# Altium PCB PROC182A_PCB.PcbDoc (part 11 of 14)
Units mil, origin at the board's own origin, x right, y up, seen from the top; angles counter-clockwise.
Board outline 3168.31 x 3700.79 mil, 8 copper layers (Top Layer, L2_GND1, L3_SIG1, L4_PWR1, L5_PWR2, L6_SIG2, L7_GND2, Bottom Layer), stack 58.1 mil thick; 580 components, 391 nets, 8314 pads, 4370 vias.
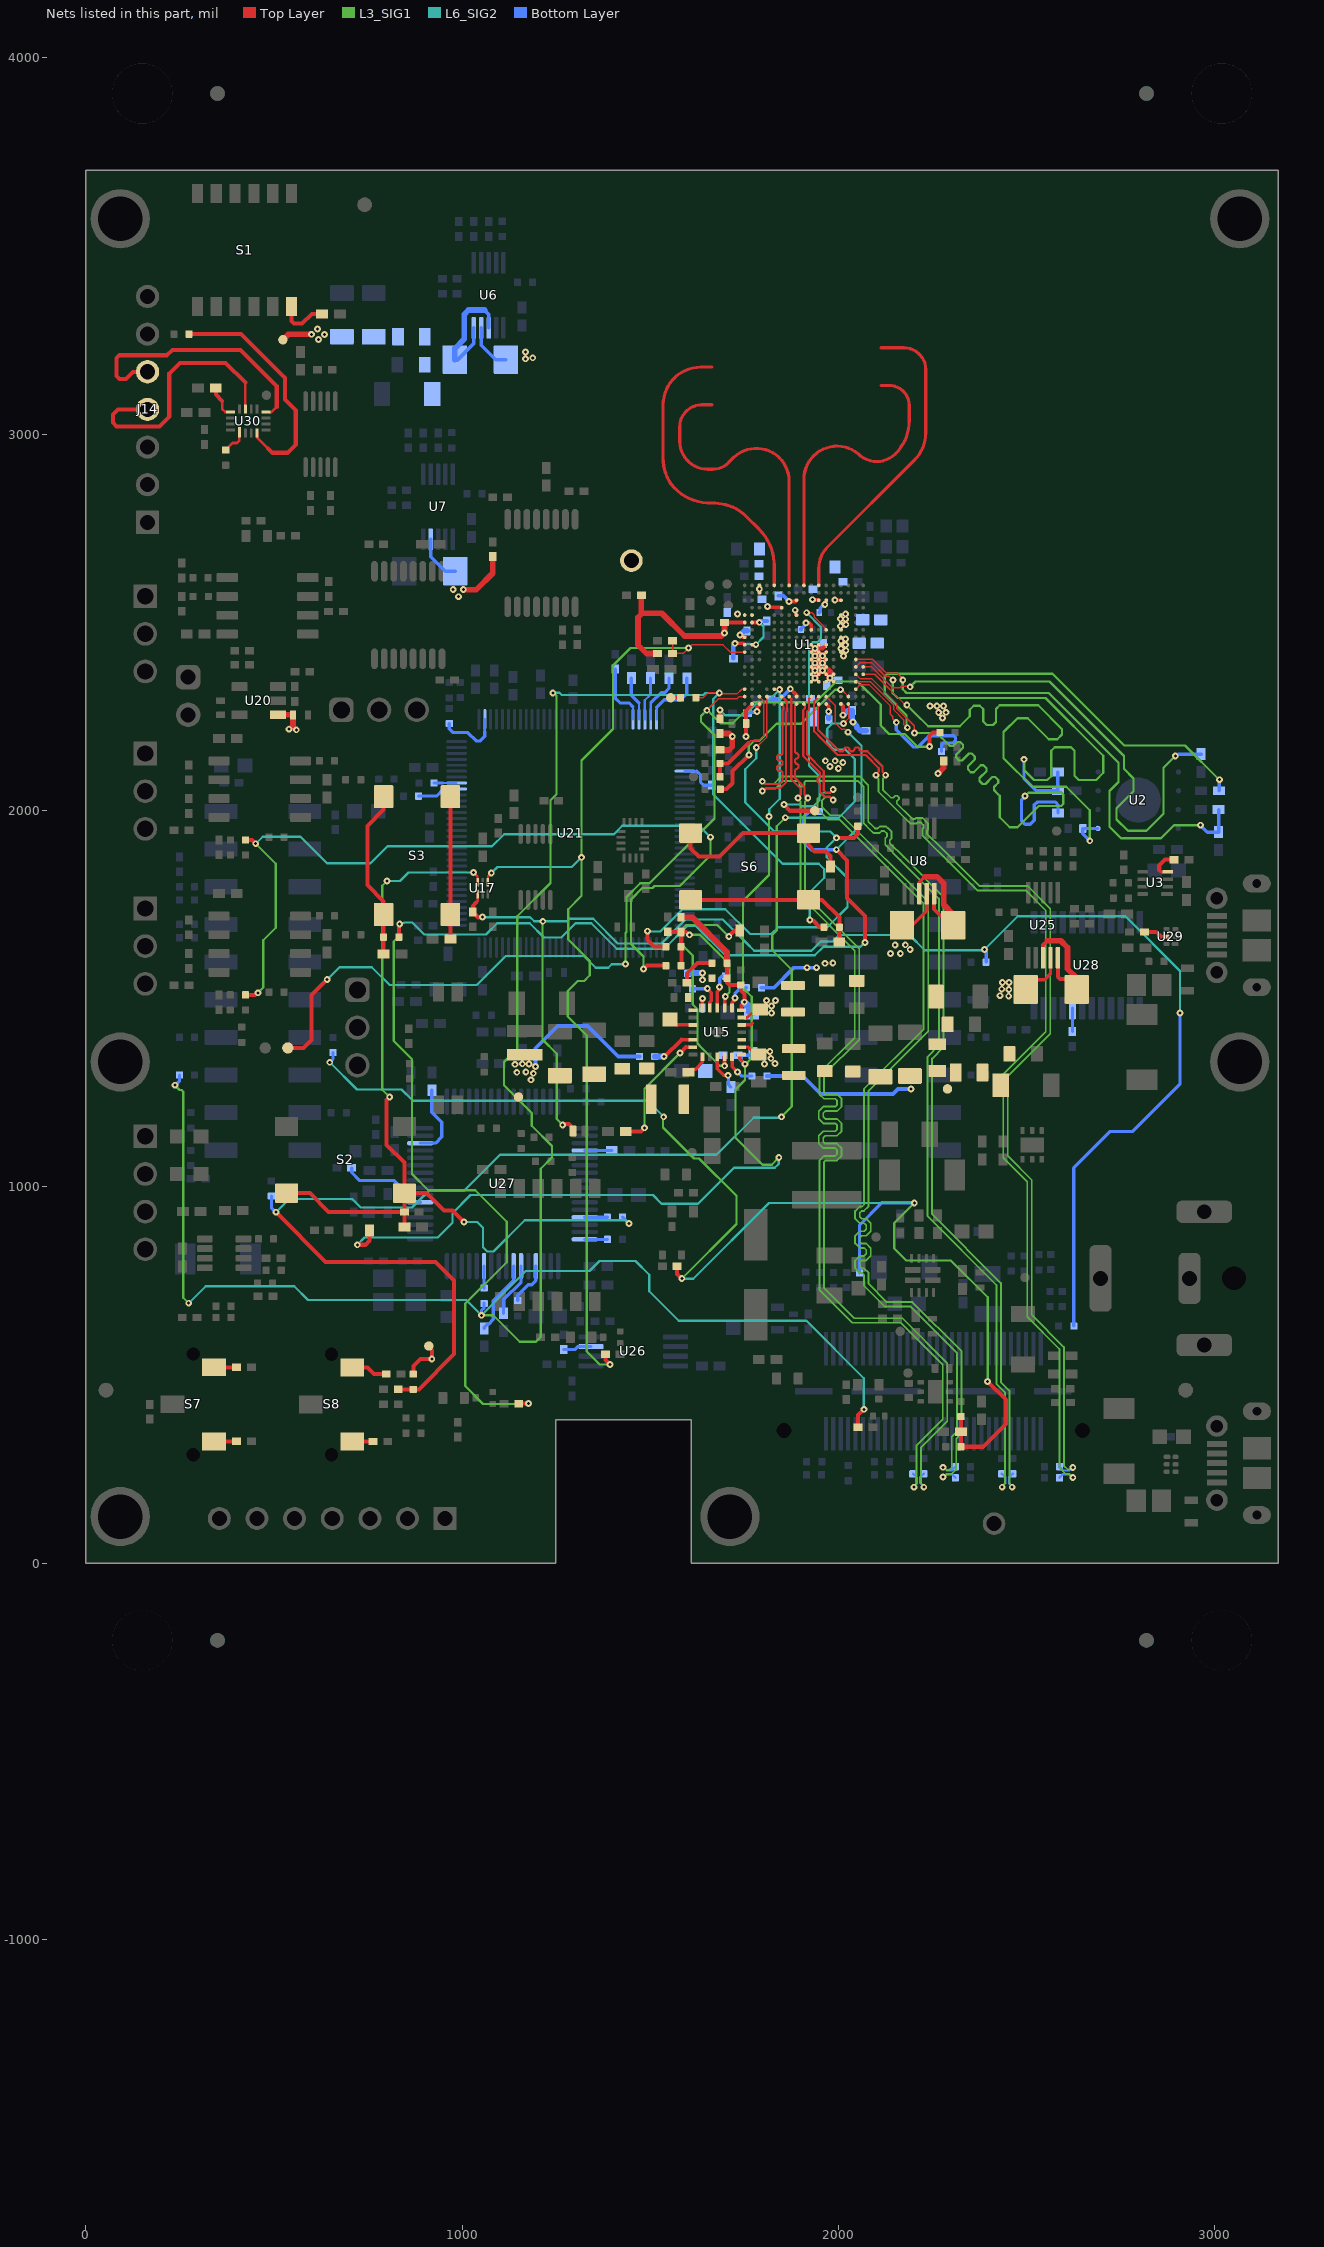
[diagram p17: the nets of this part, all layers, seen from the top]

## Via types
v1: diameter 13.77, hole 7, Top Layer to L2_GND1, tented both sides, 3444 vias
v2: diameter 18, hole 8, Top Layer to Bottom Layer, tented both sides, 911 vias
v3: diameter 13.77, hole 7, Top Layer to L2_GND1, tented top, 9 vias
v4: diameter 19.68, hole 7.87, Top Layer to Bottom Layer, 4 vias
v5: diameter 19.68, hole 7.87, Top Layer to Bottom Layer, tented both sides, 2 vias

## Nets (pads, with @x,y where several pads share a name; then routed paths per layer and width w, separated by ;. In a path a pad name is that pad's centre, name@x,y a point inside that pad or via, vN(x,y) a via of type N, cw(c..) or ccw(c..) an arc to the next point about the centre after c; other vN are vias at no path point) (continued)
NetR185_2: R185.2 U26.3 | length 75.6
  Bottom Layer w8.7: R185.2@1270.18,567.94 1298.89,567.94 1306.87,575.92 U26.3@1342.51,575.92
NetR188_2: R188.2 U21.34 | length 171.5
  Bottom Layer w7: 1060.16,2210.26 1060.11,2210.31 1060.11,2242.42 U21.34@1060.16,2242.47
  Bottom Layer w8.7: R188.2@966.13,2231.17 966.13,2217.65 976.5,2207.27 1015.09,2207.27 1037.42,2184.95 1047.94,2184.95 1060.16,2197.17 1060.16,2210.26
NetR190_2: R190.2 U21.25 | length 60
  Bottom Layer w6: 949.41,2073.18 U21.25@985.36,2073.18
  Bottom Layer w8.7: R190.2@925.36,2073.18 949.41,2073.18
NetR191_1: R191.1 U21.63 | length 168.5
  Bottom Layer w6: U21.63@1516.86,2242.47 1516.86,2274.16
  Bottom Layer w8.7: 1516.86,2274.16 1536.79,2294.09 1581.41,2294.09 1596.96,2309.64 R191.1@1596.96,2351.67
NetR194_1: R194.1 U21.62 | length 135.1
  Bottom Layer w6: U21.62@1501.11,2242.47 1501.11,2281.03 1501.11,2285.87 1502.71,2287.47
  Bottom Layer w8.7: 1502.71,2287.47 1528.71,2313.47 1538.72,2313.47 1549.54,2324.29 R194.1@1549.54,2351.67
NetR195_1: R195.1 U21.61 | length 115.7
  Bottom Layer w6: U21.61@1485.36,2242.47 1485.36,2293.14 1500.19,2307.97 1500.19,2309.96
  Bottom Layer w8.7: 1500.19,2309.96 R195.1@1500.19,2352.01
NetR196_1: R196.1 U21.60 | length 117.8
  Bottom Layer w6: U21.60@1469.61,2242.47 1469.61,2286.77
  Bottom Layer w8.7: R196.1@1449.62,2352.01 1449.62,2306.76 1469.61,2286.77
NetR204_1: R204.1 S7.3 | length 60
  Top Layer w10.8: S7.3@340.69,520.9 R204.1@400.69,520.9
NetR205_2: R205.2 S7.1 | length 60
  Top Layer w10.8: S7.1@340.69,324.05 R205.2@400.69,324.05
NetR207_1: R207.1 S8.3 | length 97.4
  Top Layer w10.8: S8.3@708.14,520.53 748.59,520.53 765.97,503.14 R207.1@798.37,503.14
NetR208_2: R208.2 S8.1 | length 55
  Top Layer w10.8: S8.1@708.14,323.68 R208.2@763.14,323.68
NetR213_1: R213.1 S3.1 S3.2 | length 378
  Top Layer w10.8: R213.1@968.7,1658.85 S3.2@968.7,1723.85 S3.1@968.7,2036.84
NetR214_1: R214.1 R215.1 S3.3 S3.4 | length 453.7
  Top Layer w10.8: R215.1@791.54,1618.85 R214.1@791.54,1663.85 791.54,1758.63 748.37,1801.79 748.37,1959.17 791.54,2002.33 S3.3@791.54,2036.84
NetR231_1: R231.1 U21.70 | length 98.5
  Bottom Layer w6: U21.70@1591.66,2104.67 1623.66,2104.67
  Bottom Layer w8.7: 1623.66,2104.67 1633.27,2095.06 1633.27,2075.82 1641.49,2067.6 R231.1@1663.56,2067.6
NetR234_2: R234.2 U21.59 | length 166.9
  Bottom Layer w6: U21.59@1453.76,2242.57 1453.76,2276.2
  Bottom Layer w8.7: R234.2@1406.98,2375.95 1406.98,2298.79 1420.03,2285.74 1444.22,2285.74 1453.76,2276.2
NetR242_1: R242.1 U27.59 | length 58.6
  Bottom Layer w8.7: R242.1@1058.17,731.15 U27.59@1058.17,789.79
NetR251_1: R251.1 U27.36 | length 71.8
  Bottom Layer w8.7: U27.36@1325.89,1096.88 R251.1@1397.7,1096.88
NetR260_2: R260.2 U29.5 | length 64
  Top Layer w8: 2856.88,1665.25 U29.5@2871.42,1665.25
  Top Layer w10.8: R260.2@2812.48,1677.42 2844.71,1677.42 2856.88,1665.25
NetR262_1: R262.1 S6.1 S6.2 | length 518.2
  Top Layer w10.8: S6.1@1607.28,1939.96 1607.28,1899.61 1628.68,1878.21 1684.31,1878.21 1746.06,1939.96 S6.2@1920.28,1939.96 1920.28,1908.03 1936.57,1891.73 1966.78,1891.73 1979.05,1879.45 R262.1@1979.05,1851.55
NetR264_1: R264.1 R265.1 S6.3 S6.4 | length 480.4
  Top Layer w10.8: S6.3@1607.28,1762.8 S6.4@1920.28,1762.8 1956.41,1762.8 2002.1,1717.1 R264.1@2002.1,1690.47 R265.1@2002.1,1650.47
NetR267_1: R267.1 R268.1 U1.R16 | length 289.8
  Top Layer w4: 1760.77,2179.9 1766.66,2185.8 1788.8,2185.8 1800.96,2197.96 1800.96,2291.84 1790.32,2302.48 U1.R16@1789.98,2302.48
  Top Layer w10.8: R267.1@1685.31,2090.04 R268.1@1685.31,2125.04 1706.62,2125.04 1760.77,2179.18
NetR270_1: R270.1 U1.C16 | length 489.6
  Top Layer w4: v2(2005.33,2321.06) 2008.46,2321.06 2026.18,2303.33 U1.C16@2026.18,2302.84
  Top Layer w10.8: R270.1@1686.38,2056.76 1702.81,2056.76 1718.6,2072.55 1718.6,2104.58 v2(1761.8,2147.78)
  L3_SIG1 w6: v2(1761.8,2147.78) 1761.8,2171.27 1776.02,2185.48 1790.06,2185.48 1835.06,2230.48 1900.05,2230.48 1990.62,2321.06 v2(2005.33,2321.06)
NetR272_2: R272.2 U30.13 | length 88.6
  Top Layer w7: 362.58,3088.04 362.58,3066.7 370.81,3058.46 U30.13@384.62,3058.46
  Top Layer w10.8: R272.2@345.57,3122.76 345.57,3105.05 362.58,3088.04
NetR277_1: R277.1 S1.12 | length 133.4
  Top Layer w10.8: S1.12@546.89,3339.18 546.89,3300.4 553.39,3293.89 575.12,3293.89 600.88,3319.65 R277.1@628.12,3319.65
NetR280_1: R280.1 U15.5 | length 119.5
  Top Layer w9: 1582.51,1391.08 U15.5@1612.83,1391.08
  Top Layer w10.8: v2(1536.51,1346.65) 1538.07,1346.65 1582.51,1391.08
  Bottom Layer w15: R280.1@1511.75,1346.5 1511.82,1346.58 1536.44,1346.58 v2(1536.51,1346.65)
NetR281_1: R281.1 U15.20 | length 76.4
  Top Layer w9: U15.20@1717.16,1477.26 1717.16,1490.04 1723.34,1496.22 1723.34,1500.66 v2(1725.06,1502.39)
  Bottom Layer w8.7: v2(1725.06,1502.39) 1725.06,1514.33 1739.74,1529 R281.1@1755.03,1529
NetR282_1: R282.1 U15.12 | length 86.6
  Top Layer w9: U15.12@1717.16,1344.27 1717.16,1319.65 v2(1731.45,1305.36)
  Bottom Layer w8.7: v2@1731.93,1304.88 1741.91,1294.91 R282.1@1769.54,1294.91
NetR283_2: R283.2 U3.4 | length 84.6
  Top Layer w8: 2850.96,1842.67 2856.39,1837.23 U3.4@2874.89,1837.23
  Top Layer w10.8: 2850.96,1842.67 2850.96,1853.79 2866.84,1869.68 R283.2@2891.69,1869.68
NetR284_2: R284.2 U1.B15 | length 446.8
  Top Layer w4: U1.B15@2046.31,2322.53 2056.61,2333.66 2082.12,2333.66 2137.86,2277.92 2137.86,2255.71 2144.24,2249.32 2144.24,2243.77 v2(2153.48,2234.47) v2(2153.48,2234.47)
  Bottom Layer w8.7: v2(2153.48,2234.47) 2153.48,2214.65 2199.41,2168.71 2202.13,2168.71 2210.72,2168.71 2240.64,2198.64 2305.74,2198.64 2310.87,2193.51 2310.87,2186.3 2304.15,2179.59 2278.89,2179.59 2273.8,2174.49 R284.2@2273.8,2157
NetR290_2: R290.2 U21.24 | length 109
  Bottom Layer w6: 950.87,2057.43 U21.24@985.36,2057.43
  Bottom Layer w8.7: R290.2@884.27,2038.44 931.88,2038.44 950.87,2057.43
NRST_FTDI: R243.1 U27.45 | length 60
  Bottom Layer w8.7: U27.45@1325.89,919.71 R243.1@1385.89,919.71
PGOOD: R58.1 R91.1 R92.2 R179.1 R211.2 R241.1 | length 3619.1
  Top Layer w10.8: R179.1@1571.28,789.67 1571.28,768.83 v2(1583.64,756.46) ; R241.1@2325.23,389.25 2325.23,388.58 2325.17,388.52 R92.2@2325.17,349.8 R91.1@2325.17,309.8 2384.34,309.8 2444.32,369.78 2444.32,434.76 2398.07,481 2397.73,481 v2(2395.55,483.18)
  L3_SIG1 w6: v2(1535.63,1186.5) 1533.78,1184.65 1533.78,1158.2 1616.08,1075.9 1629.55,1075.9 1728.95,976.5 1728.95,901.77 v2(1583.64,756.46) ; v2(2201.24,957.52) 2147.77,904.05 2147.77,836.81 2179.65,804.93 2298.22,804.93 2396.11,707.03 2396.11,483.75 v2(2395.55,483.18)
  L6_SIG2 w6: v2(648.32,1331.22) 720.51,1259.04 839.25,1259.04 869.33,1228.95 1493.18,1228.95 v2(1535.63,1186.5) ; v2(1583.64,756.46) 1614.22,756.46 1815.29,957.52 v2(2201.24,957.52)
  Bottom Layer w8.7: v2(648.32,1331.22) 657,1339.9 R211.2@657,1357.1 ; R58.1@2055.7,771.66 2055.7,898.65 2114.84,957.78 2200.98,957.78 v2(2201.24,957.52)
PMIC_B1_SW: C69.2 L5.1 U15.8 | length 59.9
  Top Layer w9: C69.2@1601.95,1305.94 1609.13,1313.11 1620.2,1313.11 1638.42,1331.33 U15.8@1638.42,1344.27
PMIC_B2_SW: L11.1 U15.17 | length 30.3
  Top Layer w9: U15.17@1742.75,1430.45 1767.36,1430.45 1771.38,1434.47
PMIC_B3_SW: L6.1 U15.15
PMIC_CAN_STB_CTRL: R85.1 R131.1 R273.1 | length 2372.2
  Top Layer w10.8: R131.1@424.37,1510.14 449.69,1510.14 455.48,1515.94 v2(457.43,1515.94) ; R273.1@424.54,1921.85 441.64,1921.85 v2(451.65,1911.85) ; v2(1481.88,1579.37) 1490.63,1588.12 R85.1@1541.14,1588.12
  L3_SIG1 w6: v2(451.65,1911.85) 504.7,1858.79 504.7,1688.45 471.43,1655.18 471.43,1529.94 v2(457.43,1515.94) ; v2(1481.88,1579.37) 1481.88,1612.09 1448.53,1645.45 1448.53,1763.77 1478.78,1794.02 1505.83,1794.02 1511.21,1799.4 1578.36,1799.4 1659.92,1880.97 v2(1659.92,1929.34)
  L6_SIG2 w6: v2(451.65,1911.85) 470.2,1930.4 570.6,1930.4 640.88,1860.13 756.54,1860.13 801.45,1905.03 1079.48,1905.03 1111.69,1937.23 1403.22,1937.23 1425.36,1959.38 1629.89,1959.38 v2(1659.92,1929.34)
PMIC_CLKOUT: R15.2 TP1.1 | length 116
  Top Layer w10.8: R15.2@870.34,502.74 870.34,524.01 889.17,542.84 v2(919.42,542.84) 919.42,565.6 911.49,573.54 TP1.1@911.49,577.38
PMIC_CLKOUT_SOP1: R15.1 R206.1 R240.2 U1.C17 | length 3838
  Top Layer w4: v2(2013.44,2231.36) 2013.44,2231.64 2026.54,2244.73 2026.54,2282.81 U1.C17@2026.18,2283.16
  Top Layer w10.8: v2(505.64,932.86) 637.32,801.18 929.19,801.18 978.7,751.66 978.7,555.96 885.13,462.39 R206.1@830.34,462.39
  L3_SIG1 w6: v2(1848.36,1186.34) 1875.71,1213.7 1875.71,1576.91 1823.91,1628.71 1823.91,1668.99 1835.96,1681.04 1835.96,1958.54 1858.5,1981.07 v2(1858.57,1981.07)
  L6_SIG2 w6: v2(505.64,932.86) 540.92,968.14 708.35,968.14 730.79,945.7 866.86,945.7 911.78,990.62 1005.66,990.62 1100.63,1085.6 1675.93,1085.6 1774.54,1184.21 1846.22,1184.21 v2(1848.36,1186.34) ; v2(1858.57,1981.07) 2000.52,1981.07 2043.2,2023.75 2043.2,2136.98 2018.32,2161.86 1988.9,2161.86 1969.83,2180.94 1969.83,2217.95 1983.24,2231.36 v2(2013.44,2231.36)
  Bottom Layer w8.7: R240.2@493.41,975.94 493.41,945.1 v2(505.64,932.86)
PMIC_EN: R145.1 U15.10 | length 102
  Top Layer w9: U15.10@1677.79,1345.81 1677.79,1314.03 1694.7,1297.13 1705.58,1297.13 v2(1706.2,1296.52)
  Bottom Layer w8.7: v2(1706.2,1296.52) 1707.97,1294.74 1707.97,1271.6 1707.82,1271.44 R145.1@1713.97,1265.29
PMIC_LS_3V3: C87.1 L14.1 R77.1 U15.1 | length 101.7
  Top Layer w10: L14.1@1597.75,1542.75 1597.75,1567.55 1624.98,1594.78 R77.1@1663.42,1594.79
PMIC_nINT_GPIO: R54.1 R57.2 R85.2 R245.2 U15.21 | length 411.7
  Top Layer w9: U15.21@1697.48,1475.73 1697.48,1498.36 1697.57,1498.45 1697.57,1501.68 1699.29,1503.4 v2(1699.29,1505.84)
  Top Layer w10.8: R57.2@1546.55,1678.18 1547.55,1677.18 1594.83,1677.18 1602.23,1669.79 v2(1603.7,1669.79) ; R85.2@1581.49,1588.12 1582.77,1589.39 1582.77,1636.96 R245.2@1581.55,1638.18 1582.34,1638.97 R54.1@1582.34,1677.38
  L3_SIG1 w6: v2(1603.7,1669.79) 1632.22,1669.79 1710.53,1591.48 1710.53,1517.07 v2(1699.29,1505.84)
PMIC_NRST_OUT: R87.1 U15.6 | length 330.3
  Top Layer w9: 1595.19,1371.4 U15.6@1611.3,1371.4
  Top Layer w10.8: R87.1@1434.58,1147.76 1474.87,1147.76 v2(1484.36,1157.26) ; v2(1579.15,1356.04) 1579.84,1356.04 1595.19,1371.4
  L3_SIG1 w6: v2(1484.36,1157.26) 1484.36,1261.26 v2(1579.15,1356.04)
PMIC_OUT_1V2: C76.1 C89.1 C90.1 C156.2 FB2.1 FB3.1 L6.2 R282.2 TP19.1 | length 408
  Bottom Layer w10: R282.2@1809.89,1294.91 1905.12,1294.91 1952.98,1247.05 2145.04,1247.05 2158.34,1260.34 v2(2192.55,1260.34)
PMIC_OUT_1V8: C80.1 C81.1 C83.1 C155.2 FB1.1 L11.2 R281.2 TP18.1 | length 250
  Top Layer w15: TP18.1@523.76,3250.69 538.31,3265.24 v2(599.58,3265.24)
  Bottom Layer w10: R281.2@1795.38,1529 1827.93,1529 1881.62,1582.69 v2(1941.28,1582.69)
  other v2: 1916.15,1582.69 1963.77,1594.29 1984.85,1594.85 618.42,3251.16 634.66,3265.02 615.78,3279.52
PMIC_OUT_3V3: C51.1 C70.1 C71.1 C75.2 C77.2 C78.2 C79.1 C117.2 L4.1 L5.2 R278.2 R279.1 R280.2 TP16.1 U15.14 U15.18 U15.24 U20.1 | length 582.5
  Top Layer w8: U15.14@1744.29,1371.4 1760.94,1371.4 1766.45,1365.89 ; U15.18@1744.29,1450.14 1757.23,1450.14 1767.42,1460.33 1768.06,1460.33
  Top Layer w9: U15.24@1638.42,1477.26 1638.42,1483 1638.38,1483.04 v2@1638.38,1500.38 ; v2(1638.34,1500.42) v2@1638.38,1500.38
  Top Layer w15: U20.1@510.67,2254.41 C51.1@550.67,2254.41 550.67,2226.44 v2(540.31,2216.08)
  Bottom Layer w10: v2(1194.88,1320.03) 1194.88,1368.31 1253.92,1427.35 1333.84,1427.35 1414.68,1346.5 R280.2@1471.4,1346.5
  Bottom Layer w15: R279.1@1599.23,1567.72 1610.91,1567.72 1614.1,1570.91 1615.91,1570.91 1618.41,1568.4 1638.2,1568.4 v2(1638.34,1568.26)
  other v2: 1182.93,1284.76 1189.05,1301.82 1145.15,1304.75 1169.16,1305.36 1140.52,1325.75 1159.82,1327.16 1177.9,1326.36 1803.68,1326.92 1831.03,1327.84 1820.18,1341.8 1817.48,1359.66 1821.57,1462.1 1822.28,1480.41 1832.47,1495.25 1808.61,1495.69 1638.52,1550.26 559.34,2214.62
PMIC_RADAR_nINT: R245.1 R257.1 U1.P16 | length 1577.3
  Top Layer w4: v2(1781.49,2167.2) 1809.65,2195.33 U1.P16@1809.65,2302.84
  Top Layer w10.8: v2(1492.61,1679.44) 1492.61,1656.73 1510.07,1639.27 1540.1,1639.27 R245.1@1541.2,1638.18 ; v2(1994.65,1927.5) 2041.03,1927.5 2051.07,1937.53 R257.1@2051.07,1958.29
  L6_SIG2 w6: v2(1492.61,1679.44) 1493.35,1678.69 1526.49,1678.69 1585.73,1737.94 1699.2,1737.94 1765.18,1671.95 1822.07,1671.95 1839.99,1689.87 1970.05,1689.87 2023.75,1743.57 2023.75,1820.98 1969.02,1875.72 1969.02,1901.87 v2(1994.65,1927.5) 1977.67,1944.48 1829.02,1944.48 1754.7,2018.79 1752.02,2021.48 1752.02,2109.48 1781.49,2138.96 v2(1781.49,2167.2)
PMIC_SCL: R89.2 U15.23 | length 95.8
  Top Layer w9: v2(1651.39,1526.96) 1662.31,1516.04 1662.31,1494.64 1658.02,1490.36 U15.23@1658.02,1476.36
  Bottom Layer w8.7: R89.2@1612,1526.47 v2@1650.89,1526.47
PMIC_SDA: R90.2 U15.22 | length 99.6
  Top Layer w9: U15.22@1677.79,1475.73 1677.79,1518.96 1682.72,1523.89 1682.72,1529.52 v2(1684.1,1530.9)
  Bottom Layer w8.7: v2(1684.1,1530.9) 1684.1,1554.91 1689.19,1560.01 R90.2@1699.78,1560.01
PMIC_VDD_1V8: C73.1 U15.3 | length 66.7
  Top Layer w9: C73.1@1552.08,1444.71 1566.34,1430.45 U15.3@1612.83,1430.45
PMIC_VIO_3V3: C100.1 R54.2 R77.2 R83.2 R278.1 U15.19 | length 391.3
  Top Layer w10: 1703.94,1583.96 R278.1@1703.94,1554.82 1703.94,1542.32 1709.71,1536.55 R83.2@1740.44,1536.55 1740.44,1521.7 1749.85,1512.28 v2@1749.85,1490.96 ; U15.19@1742.26,1469.82 1742.26,1482.19 1749.45,1489.38 v2@1749.45,1490.96
  Top Layer w15: R54.2@1581.55,1716.55 1611.54,1716.55 1703.88,1624.21 1703.88,1594.85 1703.94,1594.79 1703.94,1583.96
  Bottom Layer w20: v2(1749.76,1490.96) 1759.07,1481.64 1759.07,1471.75 1767.78,1463.05 C100.1@1768.76,1463.05
PMIC_VREG_5V0: C88.2 R76.1 R288.2 U15.11 | length 622.7
  Top Layer w10.8: v2(1697.52,1321.88) U15.11@1697.48,1345.81 ; v2(1708.38,1665.63) 1708.38,1666.31 1723.33,1681.25 R76.1@1737.64,1681.25
  L3_SIG1 w6: v2(1697.52,1321.88) 1684.33,1321.88 1636.16,1370.05 1625.19,1381.02 1625.19,1471.93 1612.36,1484.76 1612.36,1614.96 1579.85,1647.48 1579.85,1680.33 1595.62,1696.1 1677.91,1696.1 v2(1708.38,1665.63)
QSPI_CS: R50.2 U1.A13 U2.1 | length 1457.3
  Top Layer w4: U1.A13@2065.55,2361.9 2096.36,2361.9 2177.54,2280.72 v2(2181.32,2280.72)
  L3_SIG1 w6: v2(2181.32,2280.72) 2202.13,2259.91 2238.2,2223.85 2321.79,2223.85 2348.42,2250.48 2348.42,2267.75 2359.4,2278.73 2375.4,2278.73 2384.53,2269.6 2384.53,2236.48 2393.65,2227.36 2410.16,2227.36 2418.31,2235.51 2418.31,2269.69 2428.15,2279.53 2530.51,2279.53 2593.73,2216.31 2593.73,2202.1 2580.93,2189.31 2558.73,2189.31 2502.52,2245.52 2475.54,2245.52 2438.56,2208.53 2438.56,2139.17 2514.73,2062.99 2605.32,2062.99 2667.51,2000.8 v2(2667.51,1919.67)
  Bottom Layer w8.7: v2(2667.51,1919.67) 2649.15,1938.03 R50.2@2649.15,1952.59 U2.1@2689.15,1952.59
QSPI_D0: R45.2 U1.A12 | length 1396.6
  Top Layer w4: U1.A12@2065.55,2381.58 2087.99,2381.58 2142.82,2326.75 2163.33,2326.75 2167.5,2330.92 2188.33,2330.92 v2(2190.36,2328.89)
  L3_SIG1 w6: v2(2190.36,2328.89) 2204.18,2342.71 2560.3,2342.71 2758.33,2144.69 2758.33,2110.95 2783.78,2085.5 2783.78,2051.51 2738.41,2006.14 2738.41,1976.47 2768.76,1946.11 2817.89,1946.11 2863.61,1991.83 2863.61,2113.61 v2(2894.69,2144.69)
  Bottom Layer w8.7: v2(2894.69,2144.69) 2897.2,2144.69 2902.35,2149.83 R45.2@2963.3,2149.83
QSPI_D1: R46.1 U1.B13 | length 1395.8
  Top Layer w4: U1.B13@2045.87,2361.9 2057.14,2350.63 2087.78,2350.63 2154.13,2284.27 2154.13,2271.96 2201.01,2225.08 2201.01,2207.39 v2(2202.11,2206.29)
  L3_SIG1 w6: v2(2202.11,2206.29) 2261.23,2206.29 2294.16,2173.37 2296.28,2171.24 2304.06,2171.24 2315.27,2182.46 2323.05,2182.46 2330.83,2174.68 2330.83,2166.9 2312.54,2148.62 2312.54,2140.84 2320.32,2133.06 2328.1,2133.06 2346.38,2151.35 2354.16,2151.35 2361.94,2143.57 2361.94,2135.79 2343.65,2117.5 2343.65,2109.73 2351.43,2101.95 2359.21,2101.95 2377.5,2120.23 2385.27,2120.23 2393.05,2112.46 2393.05,2104.68 2374.77,2086.39 2374.77,2078.61 2382.54,2070.83 2390.32,2070.83 2408.61,2089.12 2416.39,2089.12 2424.16,2081.34 2424.16,2073.57 2412.95,2062.35 2412.95,2054.57 2423.23,2044.29 2428.07,2039.45 2428.07,2010.92 ; 2428.04,2010.89 2428.04,1982.25 2454.58,1955.71 2475.49,1955.71 2531.65,2011.88 2591.7,2011.88 2597.09,2017.26 2597.09,2042.57 2592.36,2047.3 2504.52,2047.3 v2(2495.72,2038.5)
  Bottom Layer w8.7: v2(2495.72,2038.5) 2486.22,2029 2486.22,1972.69 2495.14,1963.77 2509.87,1963.77 2520.06,1973.96 2520.06,2015.08 2527.51,2022.52 2576.59,2022.52 2583.08,2016.03 R46.1@2583.08,1993.38
QSPI_D2: R44.1 R47.1 U1.B12 | length 1443.7
  Top Layer w4: U1.B12@2045.87,2381.58 2057.5,2393.22 2087.67,2393.22 2124.22,2356.66 2134.41,2356.66 v2(2144.36,2346.72)
  L3_SIG1 w6: v2(2144.36,2346.72) 2144.36,2311.48 2157.11,2298.72 2202.13,2298.72 2550.12,2298.72 2703.19,2145.65 2703.19,2100.3 2684.4,2081.51 2638.2,2081.51 2626.94,2092.77 2626.94,2158.9 2617.3,2168.53 2574.32,2168.53 2564.92,2159.13 2564.92,2091.26 2554.6,2080.94 2519.56,2080.94 2492.49,2108.01 v2(2492.54,2136.2) v2(2492.54,2136.2)
  Bottom Layer w8.7: v2(2492.54,2136.2) v2(2492.54,2136.2) 2492.49,2085.87 2525.77,2052.59 R47.1@2582.68,2052.59 R44.1@2582.68,2102.59
QSPI_D3: R49.1 R51.2 U1.B11 | length 1393.6
  Top Layer w4: U1.B11@2045.87,2401.27 2046.99,2402.39 2051.01,2402.39 2051.13,2402.51 2089.69,2402.51 2127.54,2364.66 2156.39,2364.66 2170.63,2350.42 v2(2170.63,2346.72)
  L3_SIG1 w6: v2(2170.63,2346.72) 2170.61,2322.02 2180.48,2312.14 2202.13,2312.14 2558.48,2312.14 2743.75,2126.88 2743.75,2075.7 2719.84,2051.79 2719.84,1957.01 2750.23,1926.61 2856.71,1926.61 2891.33,1961.23 v2(2961.35,1961.23)
  Bottom Layer w8.7: v2(2961.35,1961.23) 2979.99,1942.59 R49.1@3009.77,1942.59 R51.2@3009.77,2002.59
QSPI_SCLK: R48.2 U1.B14 | length 1402.5
  Top Layer w4: U1.B14@2045.87,2342.21 2046.28,2342.63 2084.46,2342.63 2146.07,2281.02 2146.07,2268.29 2172.83,2241.54 2172.83,2228.37 2180.91,2220.29 v2(2182.64,2220.29)
  L3_SIG1 w6: v2(2182.64,2220.29) 2180.49,2222.44 2180.49,2253.02 2122.5,2311.01 2122.5,2356.53 2129.46,2363.49 2202.13,2363.49 2568.48,2363.49 2758.91,2173.05 2920.61,2173.05 v2(3011.76,2081.91)
  Bottom Layer w8.7: R48.2@3010.55,2052.59 3011.76,2053.81 v2(3011.76,2081.91)
RADAR_1P2_RF: C24.2 C44.1 R134.2 U1.D8 U1.D9 U1.D10 U25.9 | length 125.7
  Top Layer w9: R134.2@2497.43,1524.68 2523.16,1550.42 2547.39,1550.42 2563.14,1566.17 U25.9@2563.14,1609.02
  other v2: 2452.15,1506.86 2429.01,1508.05 2452.48,1524.86 2433.63,1525.44 2435.07,1543.43 2453.14,1543.31 2276.46,2245.58 2265.95,2260.39 2285.83,2260.95 2243.08,2277.72 2261.08,2277.72 2279.08,2277.63 2012.94,2410.83 2019.39,2425.11 2006.5,2430.66 2018.7,2440.29 2006.5,2450.48 2018.7,2455.46
RADAR_1V2: C2.2 C25.2 C26.2 C45.2 C121.2 C128.1 C130.1 C131.2 R193.2 U1.E13 U1.E14 U1.F9 U1.F10 U1.F11 U1.F12 U1.F13 U1.F14 U1.G9 U1.G10 U1.G11 U1.G12 U1.G13 U1.G14 U1.H9 U1.H10 U1.H11 U1.H12 U1.H13 U1.H14 U1.T5 U1.T6 U1.T9 U1.U5 U1.U9 U8.9 | length 954.7
  Top Layer w8: U1.T5@1768.35,2519.38 U1.T5@1770.28,2519.38
  Top Layer w9: R193.2@2168.58,1694.93 2195.74,1694.93 2234.29,1733.48 U8.9@2234.29,1779.27
  Top Layer w10: v2(1725.16,2444.42) 1746.81,2444.42 U1.U9@1750.59,2440.64 ; U1.T9@1770.28,2440.64 v2(1780.12,2440.64) ; U1.T6@1770.28,2499.69 1789.33,2499.69 v2(1789.66,2500.02) ; U1.H14@1927.76,2342.21 v2(1937.6,2352.06) ; U1.H9@1927.76,2440.64 v2(1937.6,2430.8) ; U1.G14@1947.44,2342.21 v2(1937.6,2352.06) ; U1.G9@1947.44,2440.64 v2(1937.6,2430.8) ; U1.F14@1967.13,2342.21 v2(1976.97,2352.06) ; U1.F10@1967.13,2420.95 v2(1957.29,2411.11) ; U1.F9@1967.13,2440.64 1957.29,2430.8 v2(1937.6,2430.8) ; U1.E14@1986.81,2342.21 v2(1976.97,2352.06) ; v2(1937.6,2352.06) U1.G13@1947.44,2361.9 ; v2(1937.6,2352.06) U1.H13@1927.76,2361.9 v2(1937.6,2371.74) ; v2(1937.6,2371.74) U1.G12@1947.44,2381.58 ; v2(1937.6,2371.74) U1.H12@1927.76,2381.58 v2(1937.6,2391.43) ; v2(1937.6,2371.74) U1.G13@1947.44,2361.9 ; v2(1937.6,2391.43) U1.H11@1927.76,2401.27 v2(1937.6,2411.11) ; v2(1937.6,2391.43) U1.G11@1947.44,2401.27 ; v2(1937.6,2391.43) U1.G12@1947.44,2381.58 ; v2(1937.6,2411.11) U1.H10@1927.76,2420.95 v2(1937.6,2430.8) ; v2(1937.6,2411.11) U1.G10@1947.44,2420.95 ; v2(1937.6,2411.11) U1.G11@1947.44,2401.27 ; v2(1937.6,2430.8) U1.G10@1947.44,2420.95 ; U1.G13@1947.44,2361.9 v2(1957.29,2371.74) ; U1.G12@1947.44,2381.58 v2(1957.29,2391.43) ; U1.G12@1947.44,2381.58 v2(1957.29,2371.74) ; U1.G11@1947.44,2401.27 v2(1957.29,2411.11) ; U1.G11@1947.44,2401.27 v2(1957.29,2391.43) ; U1.G10@1947.44,2420.95 v2(1957.29,2411.11) ; v2(1957.29,2371.74) U1.F12@1967.13,2381.58 ; v2(1957.29,2371.74) U1.F13@1967.13,2361.9 ; v2(1957.29,2391.43) U1.F11@1967.13,2401.27 v2(1957.29,2411.11) ; v2(1957.29,2391.43) U1.F12@1967.13,2381.58 ; U1.F13@1967.13,2361.9 1976.97,2371.74 ; U1.F13@1967.13,2361.9 v2(1976.97,2352.06) ; U1.F12@1967.13,2381.58 1976.97,2371.74 ; v2(1976.97,2352.06) U1.E13@1986.81,2361.9 1976.97,2371.74
  L6_SIG2 w6: v2(1725.16,2444.42) 1727.05,2442.53 1778.23,2442.53 v2(1780.12,2440.64) 1800.53,2461.05 1800.53,2489.15 v2(1789.66,2500.02)
  Bottom Layer w10: v2(1789.66,2500.02) 1791.82,2500.02 1795.49,2503.69 C25.2@1809.62,2503.69
  Bottom Layer w12: C26.2@1720.89,2404.07 1720.89,2438.53 1725.16,2442.79 v2(1725.16,2444.42)
  other v2: 2138.06,1620.31 2164.25,1620.31 2190.37,1630.86 2150.63,1642.99 2177.48,1643.42 1999.34,2111.89 1977.11,2116.93 2011.4,2127.59 1964.89,2132.12 1991.08,2132.12 1731.31,2522.11
RADAR_1V4_APLL: C22.2 U1.H7 | length 53.5
  Top Layer w10: v2(1913.62,2498.82) 1915.15,2497.29 1923.43,2497.29 1927.76,2492.96 U1.H7@1927.76,2480.01
  Bottom Layer w10: C22.2@1899.95,2481.01 1899.95,2482.98 1902.82,2485.85 1903.77,2485.85 1912.09,2494.18 1912.09,2497.29 v2(1913.62,2498.82)
RADAR_1V4_SYNTH: C18.2 U1.F3 | length 41.3
  Top Layer w10: v2(1963.68,2547.3) 1967.13,2550.75 U1.F3@1967.13,2558.75
  Bottom Layer w10: C18.2@1948.76,2526.3 1951.64,2529.17 1951.64,2537.45 1959.96,2545.77 1962.15,2545.77 v2(1963.68,2547.3)
RADAR_1V8: C1.2 C4.2 C5.2 C7.2 C8.2 C10.2 C11.2 C12.2 C13.1 C14.2 C15.1 R192.2 U1.D3 U1.F17 U1.G3 U1.K16 U1.M4 U1.R1 U1.R2 U1.R17 U1.U8 U6.9 | length 439.4
  Top Layer w10: v2(1738.08,2466.16) 1740.24,2466.16 1746.08,2460.32 U1.U8@1750.59,2460.32 ; v2(1783.21,2262.89) 1783.56,2263.24 1783.56,2274.39 1789.96,2280.8 U1.R17@1789.96,2283.16 ; v2@1789.48,2587.54 1789.48,2586.75 1789.96,2586.26 U1.R2@1789.96,2578.43 ; v2(1789.46,2588.28) 1789.96,2588.78 U1.R1@1789.96,2598.12 ; v2(1811.2,2542.18) 1813.36,2542.18 1815.47,2540.07 1848.01,2540.07 U1.M4@1849.02,2539.06 ; v2(1871.81,2323.6) 1888.39,2307.03 U1.K16@1888.39,2302.84 ; v2(1931.06,2560.3) 1945.89,2560.3 U1.G3@1947.44,2558.75 ; U1.F17@1967.27,2283.16 1973.78,2276.65 v2(1973.78,2262.9) ; v2(1990.2,2559.39) 1990.84,2558.75 U1.D3@2006.5,2558.75
  Bottom Layer w9: U6.9@1050.78,3282.32 1050.78,3236.53 1089.33,3197.98 R192.2@1116.49,3197.98
  Bottom Layer w10: C8.2@1758.19,2258.07 1761.48,2261.36 1781.67,2261.36 v2(1783.21,2262.89) ; C1.2@1819.94,2296.34 1845.03,2296.34 1871.81,2323.13 v2(1871.81,2323.6)
  Bottom Layer w15: v2(1738.08,2466.16) 1749.19,2477.28 C7.2@1756.9,2477.28 ; C10.2@1973.78,2245.47 v2(1973.78,2262.9)
  other v2: 1168.7,3200.31 1187.62,3202.87 1168.7,3218.31
RADAR_1V_RF_OUT: C9.2 C19.2 TP22.1 U1.D5 U1.D6 U1.D7 U1.K5 | length 14.4
  Top Layer w10: v2(1884.72,2532.32) 1886.25,2530.79 1886.25,2521.64 U1.K5@1888.39,2519.38
  other v2: 2005.47,2489.85 2019.2,2493.99 2018.83,2508.36 2005.47,2509.54 2019.05,2522.32
RADAR_3V3: C16.2 C17.2 C21.2 R146.2 R200.2 R246.2 R247.2 R250.2 R255.2 R256.2 R261.1 U1.D17 U1.T17 U1.U6 U7.9 | length 1165.5
  Top Layer w10: C16.2@1696.89,2499.69 U1.U6@1750.59,2499.69 ; v2@1754.33,2197.08 1754.42,2197.17 C17.2@1754.42,2231.45 1754.33,2231.45 1754.42,2231.53 1754.42,2265.06 1770.28,2280.91 U1.T17@1770.28,2283.16 ; U1.D17@2006.5,2283.16 2011.54,2278.12 v2(2011.54,2253.28)
  Top Layer w15: v2(1003.18,2587.04) 1037.78,2587.04 1081.26,2630.52 R256.2@1081.26,2674.5 ; R255.2@1476.19,2572.49 1476.19,2522.31 1467.17,2513.29 1467.17,2440.28 1490.16,2417.29 R250.2@1519.56,2417.29 ; 1478.18,2524.3 1530.18,2524.3 1590.6,2463.88 1688.36,2463.88 1696.09,2471.61 v2(1696.89,2471.61) C16.2@1696.89,2499.69 ; R146.2@1684.91,2161.05 1709.11,2161.05 1717.9,2169.83 1717.9,2195.61 1716.52,2196.99 1716.52,2197.57 1709.5,2204.58 R247.2@1685.11,2204.58 ; v2@2264.88,2099.15 2279.02,2113.29 R261.1@2279.02,2131.89
  Bottom Layer w9: U7.9@916.37,2720.53 916.37,2674.74 954.92,2636.19 R200.2@982.09,2636.19
  Bottom Layer w15: v2(2011.54,2253.28) 2012.1,2253.28 2024.41,2265.59 C21.2@2036.49,2265.59 2036.49,2237.66 2038.13,2236.02 v2(2038.13,2235.21) ; v2@2037.51,2235.21 v2(2038.13,2235.21) ; R246.2@2073.27,2211.9 2057.52,2211.9 2048.74,2220.69 2048.74,2224.6 v2(2038.13,2235.21)
  other v2: 2264.31,2098.58 1717.9,2196.99 1754.42,2196.99 990.07,2568.12 976.29,2587.04
RADAR_LVDS_0M: R230.2 U1.G17 | length 2654.6
  Top Layer w5.8: U1.G17@1947.44,2283.16 1947.44,2282.06 1945.41,2280.03 1945.41,2214.65 1957.21,2202.86 1976.07,2183.99 2002.42,2157.64 2004.44,2157.64 2011.07,2157.64 2014.52,2161.09 2014.52,2164.19 2017.97,2167.64 2024.87,2167.64 2028.32,2164.19 2028.32,2161.09 2031.77,2157.64 2038.67,2157.64 2042.12,2161.09 2042.12,2164.19 2045.57,2167.64 2052.47,2167.64 2055.92,2164.19 2055.92,2161.09 2059.37,2157.64 2076.07,2157.64 2116.85,2116.86 2116.85,2103.43 2125.38,2094.91 v2(2125.38,2093.94)
  L3_SIG1 w4.8: v2(2125.38,2093.94) 2125.38,2092.42 2118,2085.04 2118,2055.6 2139.42,2034.18 2145.07,2034.18 2150.4,2039.52 2156.03,2039.52 2160.35,2035.2 2160.35,2029.97 2154.81,2024.44 2154.81,2018.79 2191.51,1982.09 2195.69,1977.91 2203.05,1977.91 2205.76,1980.62 2223.05,1980.62 2237.44,1966.24 2237.44,1948.94 2234.73,1946.23 2234.73,1938.88 2272.75,1900.85 2276.93,1896.67 2304.34,1869.26 2373.76,1799.84 2502.09,1799.84 2562.37,1739.56 2562.37,1407.48 2449.39,1294.5 2449.39,1082.45 2513.32,1018.52 2513.32,660.09 2598.82,574.59 2598.82,259.79 2609.14,249.47 2613.45,249.47 2618.96,254.97 v2(2622.53,254.97)
  Bottom Layer w5.9: R230.2@2586.95,257.17 2586.95,256.68 2597.02,246.61 2612.48,246.61 2620.84,254.97 v2(2622.53,254.97)
RADAR_LVDS_0P: R229.2 U1.G16 | length 2653.2
  Top Layer w5.8: U1.G16@1947.44,2302.95 1935.15,2290.66 1935.15,2210.77 1953.07,2192.86 1969,2176.92 1998.28,2147.64 2071.92,2147.64 2106.85,2112.72 2106.85,2103.43 2099.38,2095.96 v2(2099.38,2093.94)
  L3_SIG1 w4.8: v2(2099.38,2093.94) 2099.38,2091.15 2106,2084.52 2106,2050.63 2183.03,1973.61 2187.21,1969.43 2190.72,1965.91 2208.02,1965.91 2210.73,1968.62 2218.08,1968.62 2225.44,1961.27 2225.44,1953.91 2222.73,1951.2 2222.73,1933.91 2264.27,1892.37 2268.45,1888.19 2368.79,1787.84 2497.12,1787.84 2550.37,1734.59 2550.37,1412.45 2437.39,1299.47 2437.39,1077.48 2501.32,1013.55 2501.32,655.12 2586.82,569.62 2586.82,254.82 2604.17,237.47 2613.5,237.47 v2(2622.53,228.44)
  Bottom Layer w5.9: R229.2@2586.95,227.48 2586.95,227.98 2595.79,236.81 2612.48,236.81 2620.84,228.44 v2(2622.53,228.44)
RADAR_LVDS_1M: R228.2 U1.M17 | length 2731.5
  Top Layer w5.8: v2(1797.5,2077.68) 1799.59,2077.68 1807,2070.27 1841.71,2070.27 1850.81,2079.38 1850.81,2099.58 1850.81,2102.48 1847.36,2105.93 1839.9,2105.93 1836.45,2109.38 1836.45,2116.28 1839.9,2119.73 1847.36,2119.73 1850.81,2123.18 1850.81,2130.08 1847.36,2133.53 1839.9,2133.53 1836.45,2136.98 1836.45,2143.88 1839.9,2147.33 1847.36,2147.33 1850.81,2150.78 1850.81,2164.86 1850.81,2266.12 1853.42,2268.73 1853.42,2277.74 1849.02,2282.15 U1.M17@1849.02,2283.16
  L3_SIG1 w4.8: v2(1797.5,2077.68) 1799.36,2077.68 1806.91,2070.13 1827.18,2070.13 1847.83,2090.78 1902.81,2090.78 2055.92,2090.78 2078.99,2067.72 2078.99,2018.79 2078.99,1970.74 2092.81,1956.91 2097,1952.73 2104.35,1952.73 2109.35,1957.73 2126.64,1957.73 2130.42,1953.94 2141.02,1943.34 2141.02,1926.05 2136.03,1921.05 2136.03,1913.7 2172.77,1876.96 2278.6,1771.13 2278.6,1371.12 2248.67,1341.18 2248.67,927.27 2431.43,744.51 2431.43,481.73 2454.07,459.09 2454.07,211.9 2461.32,204.65 v2(2461.32,202.49)
  Bottom Layer w5.9: v2(2461.32,202.49) 2461.32,204.17 2452.95,212.54 2452.95,228 2463.02,238.06 R228.2@2463.51,238.06
RADAR_LVDS_1P: R227.2 U1.M16 | length 2731.4
  Top Layer w5.8: v2(1797.5,2051.68) 1798.41,2051.68 1807,2060.27 1845.85,2060.27 1860.81,2075.24 1860.81,2164.86 1860.81,2261.97 1863.42,2264.59 1863.42,2281.88 1861.88,2283.43 1861.88,2290.89 1849.92,2302.84 U1.M16@1849.02,2302.84
  L3_SIG1 w4.8: v2(1797.5,2051.68) 1800.46,2051.68 1806.91,2058.13 1832.15,2058.13 1852.8,2078.78 1891.66,2078.78 1895.65,2074.79 1895.65,2067.64 1899.24,2064.06 1905.97,2064.06 1909.43,2067.52 1909.43,2074.79 1913.42,2078.78 2050.95,2078.78 2066.99,2062.75 2066.99,2018.79 2066.99,1965.77 2084.33,1948.43 2092.03,1940.73 2109.32,1940.73 2114.32,1945.73 2121.67,1945.73 2129.02,1938.37 2129.02,1931.02 2124.03,1926.02 2124.03,1908.73 2164.28,1868.47 2266.6,1766.16 2266.6,1376.09 2236.67,1346.15 2236.67,922.3 2419.43,739.54 2419.43,476.76 2442.07,454.12 2442.07,211.9 2434.79,204.62 v2(2434.79,202.49)
  Bottom Layer w5.9: R227.2@2433.83,238.06 2434.32,238.06 2443.15,229.23 2443.15,212.54 2434.79,204.17 v2(2434.79,202.49)
RADAR_LVDS_CLKM: R226.2 U1.J17 | length 2654.5
  Top Layer w5.8: U1.J17@1908.07,2283.16 1908.07,2282.06 1911.14,2279 1911.14,2272.01 1906.09,2266.96 1906.09,2145.12 1950.64,2100.57 1950.64,2091.39 1944.48,2085.23 1944.48,2076.19 1950.64,2070.03 1950.64,2049.4 1962.88,2037.16 1976.61,2037.16 v2(1985.82,2027.95)
  L3_SIG1 w4.8: v2(1985.82,2027.95) 1984.52,2027.95 1977.04,2035.43 1964.78,2035.43 1956.38,2027.04 1956.38,2009.07 1978.06,1987.39 2007.94,1987.39 2238.1,1757.24 2238.1,1413.79 2079.72,1255.41 2079.72,1007.32 2079.72,948.4 2067.5,936.17 2061.33,936.17 2056.13,930.97 2056.13,920.57 2061.33,915.37 2073.3,915.37 2085.52,903.14 2085.52,882.8 2073.3,870.57 2061.33,870.57 2056.13,865.37 2056.13,854.97 2061.33,849.77 2073.3,849.77 2085.52,837.54 2085.52,817.2 2073.3,804.97 2061.33,804.97 2056.13,799.77 2056.13,789.37 2061.33,784.17 2067.5,784.17 2079.72,771.94 2079.72,761.05 2079.72,742.87 2128.43,694.17 2196.38,694.17 2327.06,563.48 2327.06,345.83 2312.71,331.48 2312.71,249.48 2299.49,236.26 2286.66,236.26 2279.65,229.26 v2(2277.24,229.26)
  Bottom Layer w5.9: v2(2277.24,229.26) 2279.45,229.26 2287.55,237.36 2301,237.36 2310.39,227.98 R226.2@2310.39,227.48
RADAR_LVDS_CLKP: R225.2 U1.H16 | length 2654.2
  Top Layer w5.8: U1.H16@1927.76,2302.95 1921.92,2297.12 1921.92,2268.64 1916.09,2262.81 1916.09,2149.26 1960.64,2104.71 1960.64,2053.54 1967.02,2047.16 1977.27,2047.16 v2(1985.82,2055.71)
  L3_SIG1 w4.8: v2@1985.82,2055.53 1985.64,2055.53 1977.55,2047.43 1959.81,2047.43 1944.38,2032.01 1944.38,2004.1 1973.09,1975.39 2002.97,1975.39 2226.1,1752.26 2226.1,1418.76 2067.72,1260.38 2067.72,1007.32 2067.72,953.37 2062.53,948.17 2056.36,948.17 2044.13,935.94 2044.13,915.6 2056.36,903.37 2068.33,903.37 2073.52,898.17 2073.52,887.77 2068.33,882.57 2056.36,882.57 2044.13,870.34 2044.13,850 2056.36,837.77 2068.33,837.77 2073.52,832.57 2073.52,822.17 2068.33,816.97 2056.36,816.97 2044.13,804.74 2044.13,784.4 2056.36,772.17 2062.53,772.17 2067.72,766.97 2067.72,761.05 2067.72,737.9 2123.46,682.17 2191.41,682.17 2315.06,558.51 2315.06,350.8 2300.71,336.45 2300.71,254.45 2294.52,248.26 2286.66,248.26 2279.65,255.27 v2(2277.24,255.27)
  Bottom Layer w5.9: v2(2277.24,255.27) 2279.45,255.27 2287.55,247.16 2300.88,247.16 2310.39,256.68 R225.2@2310.39,257.17
RADAR_LVDS_FRCLKM: R220.2 U1.K17 | length 2732
  Top Layer w5.8: U1.K17@1888.39,2283.16 1888.39,2282.06 1884.38,2278.06 1884.38,2160.68 1884.38,2157.78 1884.39,2155.55 1887.84,2152.1 1889.97,2152.1 1893.42,2148.65 1893.42,2141.75 1889.97,2138.3 1887.81,2138.3 1884.36,2134.85 1884.36,2127.95 1887.81,2124.5 1889.97,2124.5 1893.42,2121.05 1893.42,2114.15 1889.97,2110.7 1887.88,2110.7 1884.43,2107.25 1884.45,2093.45 1884.45,2090.55 1884.45,2087.37 1909.61,2062.21 1909.61,2042.81 1918.24,2034.18 v2(1918.24,2033.27)
  L3_SIG1 w4.8: v2(1918.24,2033.27) 1918.24,2031.27 1911.1,2024.14 1911.1,2018.79 1911.1,1776.57 2054.99,1632.68 2054.99,1391.61 1961.21,1297.83 1961.21,1257.55 1961.21,1251.63 1966.41,1246.43 1995.97,1246.43 2008.2,1234.2 2008.2,1213.86 1995.97,1201.63 1964.65,1201.63 1959.45,1196.43 1959.45,1186.03 1964.65,1180.83 1995.97,1180.83 2008.2,1168.6 2008.2,1148.26 1995.97,1136.03 1964.65,1136.03 1959.45,1130.83 1959.45,1120.43 1964.65,1115.23 1995.97,1115.23 2008.2,1103 2008.2,1082.66 1995.97,1070.43 1966.41,1070.43 1961.21,1065.23 1961.21,1022.57 1961.21,731.77 2041.72,651.26 2169.88,651.26 2289.03,532.11 2289.03,378.08 2219.31,308.37 2219.31,211.75 2226.45,204.61 v2(2226.45,202.33)
  Bottom Layer w5.9: v2(2226.45,202.33) 2226.45,204.27 2217.29,213.43 2217.29,229.04 2226.31,238.06 R220.2@2226.8,238.06
RADAR_LVDS_FRCLKP: R219.2 U1.L16 | length 2731.2
  Top Layer w5.8: U1.L16@1868.7,2302.84 1874.38,2297.17 1874.38,2148.88 ; 1874.36,2148.86 1874.36,2093.91 1874.45,2093.82 1874.45,2083.23 1899.61,2058.07 1899.61,2042.76 1892.24,2035.4 v2(1892.24,2033.27)
  L3_SIG1 w4.8: v2(1892.24,2033.27) 1892.24,2030.73 1899.1,2023.87 1899.1,2018.79 1899.1,1771.6 2042.99,1627.71 2042.99,1396.58 1949.21,1302.8 1949.21,1293.39 1949.21,1257.55 1949.21,1246.66 1961.44,1234.43 1991,1234.43 1996.2,1229.23 1996.2,1218.83 1991,1213.63 1959.68,1213.63 1947.45,1201.4 1947.45,1181.06 1959.68,1168.83 1991,1168.83 1996.2,1163.63 1996.2,1153.23 1991,1148.03 1959.68,1148.03 1947.45,1135.8 1947.45,1115.46 1959.68,1103.23 1991,1103.23 1996.2,1098.03 1996.2,1087.63 1991,1082.43 1961.44,1082.43 1949.21,1070.2 1949.21,1022.57 1949.21,726.8 2036.75,639.26 2164.91,639.26 2277.03,527.14 2277.03,383.05 2207.31,313.34 2207.31,211.75 2200.18,204.61 v2(2200.18,202.33)
  Bottom Layer w5.9: R219.2@2197.61,238.06 2198.1,238.06 2207.49,228.67 2207.49,211.84 2200.18,204.53 v2(2200.18,202.33)
RADAR_nERROR_OUT: D13.1 R247.1 R288.1 R289.2 U1.N15 U15.13 | length 3064.4
  Top Layer w4: U1.N15@1829.33,2322.53 1829.67,2322.19 1843.23,2322.19 v2(1843.57,2321.85)
  Top Layer w9: U15.13@1737.58,1350.96 1737.58,1340.21 v2(1751.56,1326.23)
  Top Layer w10.8: v2(721.46,846.46) 743.22,846.46 753.92,857.15 D13.1@753.92,884.63 ; v2(1685.03,2267.3) 1685.07,2267.26 1685.07,2243.99 R247.1@1685.11,2243.95
  L3_SIG1 w6: v2(1815.43,1983.89) 1815.43,1829.05 1746.19,1759.81 1746.19,1528.76 1769.76,1505.2 1769.76,1342.91 1753.08,1326.23 v2(1751.56,1326.23) 1751.56,1284.04 1726.53,1259.01 1726.53,1130.52 1797.85,1059.2 1822.3,1059.2 v2(1841.26,1078.16)
  L6_SIG2 w6: v2(721.46,846.46) 740.94,865.94 935.39,865.94 974.62,905.18 974.62,930.5 1022.47,978.35 1506.89,978.35 1529.53,955.71 1626.97,955.71 1722.11,1050.85 1830.86,1050.85 1841.26,1061.26 v2(1841.26,1078.16) ; v2(1685.03,2267.3) 1698.87,2253.46 1751.14,2253.46 1786.45,2288.76 1810.48,2288.76 v2(1843.57,2321.85) 1843.57,2031.11 1815.72,2003.27 1815.72,1984.19 v2(1815.43,1983.89)
  Bottom Layer w10: R288.1@1732.96,1349.74 1738.46,1349.74 1767.36,1349.74 R289.2@1773.2,1355.59 ; R288.1@1738.46,1344.9 1739.77,1344.9 1739.77,1338.14 v2@1751.56,1326.35
RADAR_NRST: C134.2 R171.2 R250.1 U1.U10 U17.4 | length 2808.4
  Top Layer w4: C134.2@1558.53,2451.53 1558.93,2451.13 R250.1@1558.93,2417.29 1587.36,2417.29 v2(1601.74,2431.66) 1610.26,2440.19 1693.34,2440.19 1712.76,2420.76 1725.16,2420.75 U1.U10@1750.59,2420.73
  Top Layer w6: U17.4@1068.58,1809.55 1068.58,1824.95 v2(1077.53,1833.9)
  Top Layer w10.8: R171.2@1380.43,555.07 1380.43,540.72 v2(1392.97,528.18)
  L3_SIG1 w6: v2(1316.85,1875.78) 1317.42,1875.21 1317.42,1773.57 1281.72,1737.87 1281.72,1657.72 1339.38,1600.05 1339.38,1562.22 1324.39,1547.23 1307.32,1547.23 1280.4,1520.31 1280.4,1453.06 1330.88,1402.59 1330.88,562.65 1365.35,528.18 v2(1392.97,528.18) ; v2@1317.42,1875.78 1317.42,2132.97 1401.1,2216.65 1401.1,2385.61 1447.15,2431.66 1528.36,2431.66 v2(1601.74,2431.66)
  L6_SIG2 w6: v2(1077.53,1833.9) 1093.88,1850.25 1291.32,1850.25 v2(1316.85,1875.78)
RADAR_NRST_1: D4.2 R63.1 R123.1 R183.2 U17.1 | length 3902.9
  Top Layer w6.5: 1036.65,1755.22 1041.02,1759.59 U17.1@1041.02,1778.05
  Top Layer w10.8: 1036.65,1755.22 1028.35,1746.91 R123.1@1028.35,1730.76 1042.52,1716.59 1053.69,1716.59 v2(1054,1716.89) ; v2(1267.3,1164.83) 1269.25,1164.83 1272.04,1167.62 1284.13,1167.62 1290.6,1161.14 1290.6,1152.45 D4.2@1294.55,1148.5
  L3_SIG1 w6: v2(1214.26,1705.85) 1213.78,1705.37 1213.78,1392.07 1251.59,1354.26 1251.59,1180.54 v2(1267.3,1164.83)
  L6_SIG2 w6: v2(1054,1716.89) 1180.56,1716.89 1191.6,1705.85 v2(1214.26,1705.85) 1279.38,1705.85 1286.21,1712.67 1348.09,1712.67 1413.76,1646.99 1529.54,1646.99 1593.26,1710.71 1692.48,1710.71 1755.24,1647.95 1775.87,1627.32 1928.22,1627.32 1953,1652.09 1984.42,1652.09 2001.93,1669.6 2188.33,1669.6 2228.9,1629.03 2385.71,1629.03 v2(2387.79,1631.11) ; v2@2385.99,1629.03 2475.84,1718.88 2762.39,1718.88 2907.42,1573.84 v2(2907.42,1462.07)
  Bottom Layer w8.7: v2(2387.79,1631.11) 2387.79,1628.59 2392.35,1624.02 R183.2@2392.35,1597.45 ; R63.1@2625.01,630.51 2625.01,1050.54 2721.95,1147.48 2781.34,1147.48 2907.48,1273.62 2907.48,1462.01 v2(2907.42,1462.07)
RADAR_NRST_2: C53.1 R165.1 R243.2 S2.3 S2.4 U17.6 | length 2312.3
  Top Layer w6: v2(1030.25,1835.55) 1041.02,1824.77 U17.6@1041.02,1809.55
  Top Layer w10.8: S2.3@533.56,983.61 595.5,983.61 645.5,933.61 R165.1@846.55,933.61 ; v2(807.53,1239.04) 807.53,1238.78 799.52,1230.78 799.52,1111.71 846.55,1064.68 S2.4@846.55,983.61 ; C53.1@846.55,893.61 R165.1@846.55,933.61 ; v2@1004.83,906.64 1004.83,906.98 974.35,937.45 952.03,937.45 905.87,983.61 S2.4@846.55,983.61 ; R165.1@846.55,933.61 S2.4@846.55,983.61
  L3_SIG1 w6: v2(800.77,1813.11) 788.11,1800.45 788.11,1258.45 v2(807.53,1239.04)
  L6_SIG2 w6: v2(800.77,1813.11) 834.85,1813.11 857.28,1835.55 v2(1030.25,1835.55) ; v2(1005,906.81) 1039.94,906.81 1055.22,891.53 1055.22,839.99 1066.94,828.27 1083.5,828.27 1166.69,911.46 1434.87,911.46 v2(1443.35,902.97)
  Bottom Layer w8.7: R243.2@1426.24,919.71 1426.24,919.22 1442.49,902.97 v2(1443.35,902.97)
RADAR_OSC_CLKOUT: TP2.1 U1.F7 | length 811.8
  Top Layer w4: v2(1915.35,2525.59) 1929.31,2525.59 1935.45,2519.46 1935.45,2514.28 1964.7,2485.03 1964.7,2484.02 1967.13,2481.59 U1.F7@1967.13,2480.01
  Top Layer w10.8: v2@1855.33,2015.51 1871.4,1999.44 TP2.1@1936.9,1999.44
  L6_SIG2 w6: v2(1855.33,2015.96) 1897.3,2015.96 1902.09,2011.17 1933.2,2011.17 1940.82,2018.79 1949.13,2027.1 1949.13,2091.35 1921.6,2118.88 1921.6,2437.42 1931.66,2447.48 1943.54,2447.48 1953.6,2457.54 1953.6,2487.35 v2(1915.35,2525.59)
RADAR_SYNC_IN_GPIO_5: J15.1 R81.1 U1.U16 | length 2864.2
  Top Layer w4: v2(1650.07,2266.24) 1680.85,2297.01 1730.1,2297.01 1735.93,2302.84 U1.U16@1750.59,2302.84
  Top Layer w10.8: J15.1@536.88,1369.43 579.08,1369.43 600.39,1390.75 600.39,1510.42 v2(641.47,1551.5) ; v2(2242.04,2169.84) 2242.04,2198.67 2250.83,2207.46 R81.1@2269.3,2207.46
  L3_SIG1 w6: v2(1433.95,1592.03) 1433.95,1674.71 1436.53,1677.28 1436.53,1770.48 1472.99,1806.95 1497.95,1806.95 1670.17,1979.17 1670.17,2200.75 1634.88,2236.03 1634.88,2251.05 v2(1650.07,2266.24) 1652.07,2266.24 1686.13,2232.18 1719.09,2232.18 1774.64,2287.73 1938.97,2287.73 1994.2,2342.97 2050.49,2342.97 2111.88,2281.57 2111.88,2225.95 2134.14,2203.69 2175.68,2203.69 2209.53,2169.84 v2(2242.04,2169.84)
  L6_SIG2 w6: v2(641.47,1551.5) 673.98,1584.01 760.19,1584.01 807.92,1536.27 1038.54,1536.27 1115.88,1613.61 1323.51,1613.61 1354.98,1582.14 1387.9,1582.14 1397.79,1592.03 v2(1433.95,1592.03)
RADAR_USER_LED_GPIO_6: R222.1 R242.2 R263.2 R264.2 R269.2 U1.U15 | length 6329.3
  Top Layer w4: R269.2@1621.11,2299.95 1640.1,2299.95 1652.55,2312.41 v2(1683.22,2312.41) 1685.81,2309.82 1730.25,2309.82 1742.95,2322.53 U1.U15@1750.59,2322.53
  Top Layer w10.8: v2(1923.66,1708.93) 1925.04,1707.55 1932.81,1707.55 1949.9,1690.47 R264.2@1961.75,1690.47 ; R263.2@2052,361.35 2052,393.93 v2(2067.33,409.26)
  L3_SIG1 w6: v2(236.92,1270.33) 249.36,1257.89 254.18,1257.89 259.2,1252.87 259.2,705.58 v2(273.59,691.19) ; v2(1051.38,659.06) 1082.89,659.06 1153.02,588.92 1196.41,588.92 1208.86,601.37 1208.86,1048.56 1238.47,1078.17 1238.47,1109.12 1185.1,1162.49 1185.1,1196.32 1111.36,1270.05 1111.36,1331.76 1146.6,1366.99 1146.6,1718.95 1234.93,1807.29 1234.93,2027.34 1250.71,2043.12 1250.71,2304.67 1242.7,2312.68 v2(1240.94,2312.68)
  L6_SIG2 w6: v2(273.59,691.19) 318.7,736.3 554.11,736.3 590.67,699.74 1010.69,699.74 v2(1051.38,659.06) 1168.86,776.54 1338.55,776.54 1365.16,803.15 1460.63,803.15 1497.18,766.6 1497.18,722.76 1575.69,644.25 1915.17,644.25 2067.33,492.09 v2(2067.33,409.26) ; v2(1240.94,2312.68) 1258.51,2312.68 1264.43,2306.76 1640.48,2306.76 1646.13,2312.41 v2(1683.22,2312.41) 1667.29,2296.48 1667.29,2042.44 1690.94,2018.79 1851.28,1858.46 1947.68,1858.46 1962.19,1843.95 1962.19,1821.79 1923.66,1783.26 v2(1923.66,1708.93)
  Bottom Layer w8.7: v2(236.92,1270.33) 237.73,1270.33 249.2,1281.8 R222.1@249.2,1297.45 ; v2(1051.38,659.06) 1051.38,671.79 1058.37,678.78 R242.2@1058.37,690.79
RADAR_USER_SW_GPIO_2: R66.2 R175.1 R214.2 U1.F16 | length 4089.3
  Top Layer w4: U1.F16@1967.13,2302.84 1991.68,2278.29 1991.68,2231.91 2007.23,2216.36 2017.03,2216.36 v2(2025.2,2208.19)
  Top Layer w10.8: R214.2@831.89,1663.85 831.89,1694.66 834.13,1696.89 v2(834.13,1698.84) ; R66.2@1150.49,423.81 1151.06,424.37 1175.63,424.37 v2(1176.2,424.94) ; v2(1994.12,1896.07) 2023,1867.2 2023,1767.09 2070.23,1719.86 v2(2070.23,1649.6)
  L3_SIG1 w6: v2(834.13,1698.84) 834.13,1668.02 818.3,1652.19 818.3,1387.54 866.57,1339.27 866.57,1034.65 910.04,991.19 1035.04,991.19 1118.29,907.93 1118.29,800.17 1008.26,690.14 1008.26,471.07 1055.66,423.67 1174.93,423.67 v2(1176.2,424.94)
  L6_SIG2 w6: v2(834.13,1698.84) 836.42,1701.14 844.63,1701.14 846.35,1702.86 867.51,1702.86 899.44,1670.93 1063.67,1670.93 1093.44,1700.7 1179.78,1700.7 1217.78,1662.7 1263.33,1662.7 1301.3,1700.67 1343.11,1700.67 1411.12,1632.66 1536.76,1632.66 1597.25,1693.15 1620.94,1693.15 1698.76,1615.32 1937.06,1615.32 1959.75,1638.01 2058.64,1638.01 v2(2070.23,1649.6) ; v2(1994.12,1896.07) 2061.02,1962.96 2061.02,2172.37 v2(2025.2,2208.19)
  Bottom Layer w8.7: R175.1@1949.2,1997.45 1922.37,1997.45 1906.66,1981.74 1906.66,1916.67 1927.26,1896.07 v2(1994.12,1896.07)
RADAR_VBGAP: C6.1 U1.K3 | length 56.2
  Top Layer w10: v2(1868.56,2555.72) 1885.36,2555.72 U1.K3@1888.39,2558.75
  Bottom Layer w10: C6.1@1839.55,2570.53 1853.75,2570.53 v2(1868.56,2555.72)
REF_FTDI: R218.2 U27.6 | length 243.9
  Bottom Layer w8.7: R218.2@706.59,1050.68 706.59,1038.47 728.05,1017.01 820.01,1017.01 841.04,995.98 841.04,967.79 849.75,959.08 U27.6@888.88,959.08
REG_1V2: C20.2 C91.2 FB2.2 R193.1 U8.8 U8.10 | length 364.3
  Top Layer w10: U8.8@2214.41,1779.46 2214.41,1809.62 ; U8.8@2214.6,1779.27 2214.53,1779.35 2214.53,1809.51 2214.41,1809.62 ; 2229.15,1824.35 2214.41,1809.62 ; U8.10@2253.97,1779.27 2253.97,1737.89 R193.1@2297.72,1694.14
  Top Layer w15: 2229.15,1824.35 2261.64,1824.35 2279.5,1806.49 2279.5,1749.68 2304.4,1724.78 R193.1@2304.4,1694.93
REG_1V8: C3.2 C82.2 FB1.2 R192.1 U6.8 U6.10 | length 344.1
  Bottom Layer w10: R192.1@987.35,3197.2 1031.09,3240.94 U6.10@1031.09,3282.32 ; 1059.27,3329.66 1070.65,3318.28 U6.8@1070.65,3282.51
  Bottom Layer w15: R192.1@980.67,3197.98 980.67,3227.83 1005.56,3252.73 1005.56,3318.25 1016.98,3329.66 1059.27,3329.66
REG_RF_1V2: C27.2 C103.2 FB3.2 R134.1 U25.8 U25.10 | length 351
  Top Layer w10: U25.8@2543.46,1609.02 2543.46,1642.87 2554.69,1654.11 ; U25.10@2582.83,1609.02 2582.83,1558.23 2588.68,1552.37 2611.08,1552.37 2633.25,1530.2 R134.1@2633.25,1524.68
  Top Layer w15: 2554.69,1654.11 2590.49,1654.11 2608.35,1636.24 2608.35,1579.44 2633.25,1554.54 R134.1@2633.25,1524.68
RS232_FTDI_RX: R120.1 U27.48 | length 60
  Bottom Layer w8.7: U27.48@1325.89,860.66 R120.1@1385.89,860.66
RS232_FTDI_TX: R121.1 U27.52 | length 117.2
  Bottom Layer w8.7: R121.1@1147.74,698.12 1147.74,712.69 1175.61,740.56 1185.15,740.56 1195.96,751.37 U27.52@1195.96,789.79
RST_FTDI: R237.2 U27.14 | length 198.4
  Bottom Layer w8.7: U27.14@888.88,1116.56 929.33,1116.56 945.77,1133 945.77,1172.51 919.5,1198.78 R237.2@919.5,1256.83
RTC_CLK_IN: R269.1 TP9.1 | length 26.7
  Top Layer w10.8: TP9.1@1554.15,2299.79 1554.32,2299.95 R269.1@1580.76,2299.95
RX1: U1.N1 | length 834.8
  Top Layer w8.39: 1663.65,3177.99 1633.97,3177.99 ccw(c1633.97,3077.99) 1533.97,3077.99 1533.97,2937.15 ccw(c1659.78,2936.99) 1555.15,2867.12 ccw(c1659.17,2949.57) 1663.08,2816.9 cw(c1663.33,2808.51) 1663.23,2816.9 cw(c1664.36,2679.38) 1690.26,2814.44 cw(c1673.18,2701.1) 1754.17,2782.21 1789.45,2746.93 cw(c1693.28,2650.69) 1829,2660.18 cw(c1693.28,2650.69) 1829.33,2650.69 U1.N1@1829.33,2598.12
RX2: U1.L1 | length 834
  Top Layer w8.39: 1663.65,3077.99 1636.43,3077.99 ccw(c1636.43,3019.76) 1578.2,3019.76 1578.2,2980.86 ccw(c1652.2,2980.82) 1652.13,2906.82 1666.33,2906.82 ccw(c1666.33,2964.73) 1707.37,2923.88 ; 1707.37,2923.88 1722.13,2938.64 cw(c1728.02,2932.67) 1722.25,2938.75 cw(c1781.75,2875.35) 1868.7,2875.35 1868.7,2660.18 U1.L1@1868.7,2598.12
RX3: U1.J1 | length 834.6
  Top Layer w8.39: U1.J1@1908.07,2598.12 1908.07,2880.16 ; 1908.07,2880.2 cw(c1995.96,2880.26) 2052.5,2947.55 ccw(c2101.78,2996.85) 2101.6,2927.14 ccw(c2101.7,2996.15) 2150.38,2947.24 2150.61,2947.47 ccw(c2064,3036.14) 2187.95,3036.14 2187.95,3075.93 ccw(c2134.5,3075.93) 2134.5,3129.38 2113.1,3129.38
RX4: U1.G1 | length 834.9
  Top Layer w8.39: U1.G1@1947.44,2598.12 1947.44,2643.9 ; 1947.44,2643.94 cw(c2026.73,2643.94) 1949.12,2660.18 cw(c2026.73,2643.94) 1970.7,2700.05 2201.41,2930.75 ccw(c2128.55,3003.68) 2231.64,3003.68 2231.64,3171.64 ccw(c2173.89,3171.64) 2173.89,3229.38 2113.1,3229.38
SOP0_FTDI: R249.1 U27.55 | length 200.5
  Bottom Layer w8.7: R249.1@1058.84,623.96 1058.84,627.9 1066.3,635.36 1070.24,635.36 1082.92,648.05 1082.92,697.63 1136.91,751.62 U27.55@1136.91,789.79
SOP1_FTDI: R248.1 U27.54 | length 144.6
  Bottom Layer w8.7: R248.1@1109.7,664.65 1109.7,699.95 1156.59,746.85 U27.54@1156.59,789.79
SPI_MUX_ENn: R10.1 U28.20 | length 61.9
  Bottom Layer w8.7: R10.1@2621.55,1413.19 U28.20@2621.55,1475.05
SPIB_CLK: R285.2 U30.1 | length 69.6
  Top Layer w7: R285.2@371.87,2957.78 372.36,2957.78 378.21,2963.63 378.21,2964.13 390.46,2976.38 401.91,2976.38 408.24,2982.71 U30.1@408.24,3005.31
SPIB_CS0_N: J14.4 U30.11 | length 704.8
  Top Layer w7: U30.11@423.99,3066.34 423.99,3137.04
  Top Layer w10.8: J14.4@164.17,3065.75 86.01,3065.75 71.97,3051.7 71.97,3030.95 82.35,3020.57 196.23,3020.57 222,3046.35 222,3161.38 249.98,3189.36 371.67,3189.36 423.99,3137.04
SPIB_MISO: J14.5 U30.8 | length 703.8
  Top Layer w7: U30.8@479.11,3058.46 493.33,3058.46 507.46,3072.6
  Top Layer w10.8: J14.5@164.17,3165.75 163.82,3165.39 125.78,3165.39 106.76,3146.38 90.06,3146.38 82.21,3154.23 82.21,3201.74 90.12,3209.66 216.36,3209.66 230.05,3223.35 411.61,3223.35 507.46,3127.5 507.46,3072.6
SPIB_MOSI: R286.2 U30.4 | length 632.3
  Top Layer w7: U30.4@455.49,3003.35 455.49,2991.32 484.74,2962.06
  Top Layer w10.8: R286.2@274.53,3265.75 413.09,3265.75 529.06,3149.77 529.06,3092 558.07,3062.99 558.07,2972.72 535.9,2950.55 496.26,2950.55 484.74,2962.06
